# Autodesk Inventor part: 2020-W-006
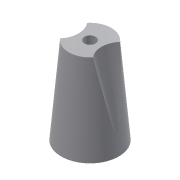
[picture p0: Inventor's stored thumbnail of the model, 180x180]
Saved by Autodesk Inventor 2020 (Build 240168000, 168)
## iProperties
Created: 2013-12
Part Number: 2020-W-006
Material: Tworzywo sztuczne ABS
Document SubType Name: Modeling
Designer: F.Stasiak
Density: 1.06 g/cm^3
Appearance: Gładki - biały
Manager: www.cadconsulting.pl
Company: Fabian Stasiak CAD Consulting
Author: F.Stasiak
Subject: Zbiór ćwiczeń. Autodesk Inventor 2020. Kurs podstawowy
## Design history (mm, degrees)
sketch "Szkic1"
  geometry: C1 r 20 at (0, 0); 1 further point
  constraints: 1 centre point, 1 coincident
  dimensions: "d0" = 40 diameter of C1
extrude "Wyciągnięcie proste1" new body sketch "Szkic1" distance "d1" = 60; taper "d2" = -5 deg
sketch "Szkic2"
  geometry: C1 r 14.751 at (0, 0) reference; C2 r 14.5 at (22.5, 0); C3 r 14.5 at (-22.5, 0); A1 r 22.5 centre (0, 0) between (22.5, 0) and (-22.5, 0)
  constraints: 3 centre point, 2 horizontal alignment, 2 point on circle, 1 coincident, 1 equal radius
  dimensions: "d3" = 45 diameter of A1; "d4" = 29 diameter of C2
extrude "Wyciągnięcie proste2" cut sketch "Szkic2" distance "d5" = 50.25; taper "d6" = -13 deg
hole "Otwór1" diameter "d9" = 8; stored, may be unused: countersink angle "d13" = 90 deg, drill point angle "d15" = 118 deg; dims "d7" = 10, "d8" = 10, "d10" = 6, "d11" = 4, "d12" = 2, "d14" = 8
node "Bryła1"
